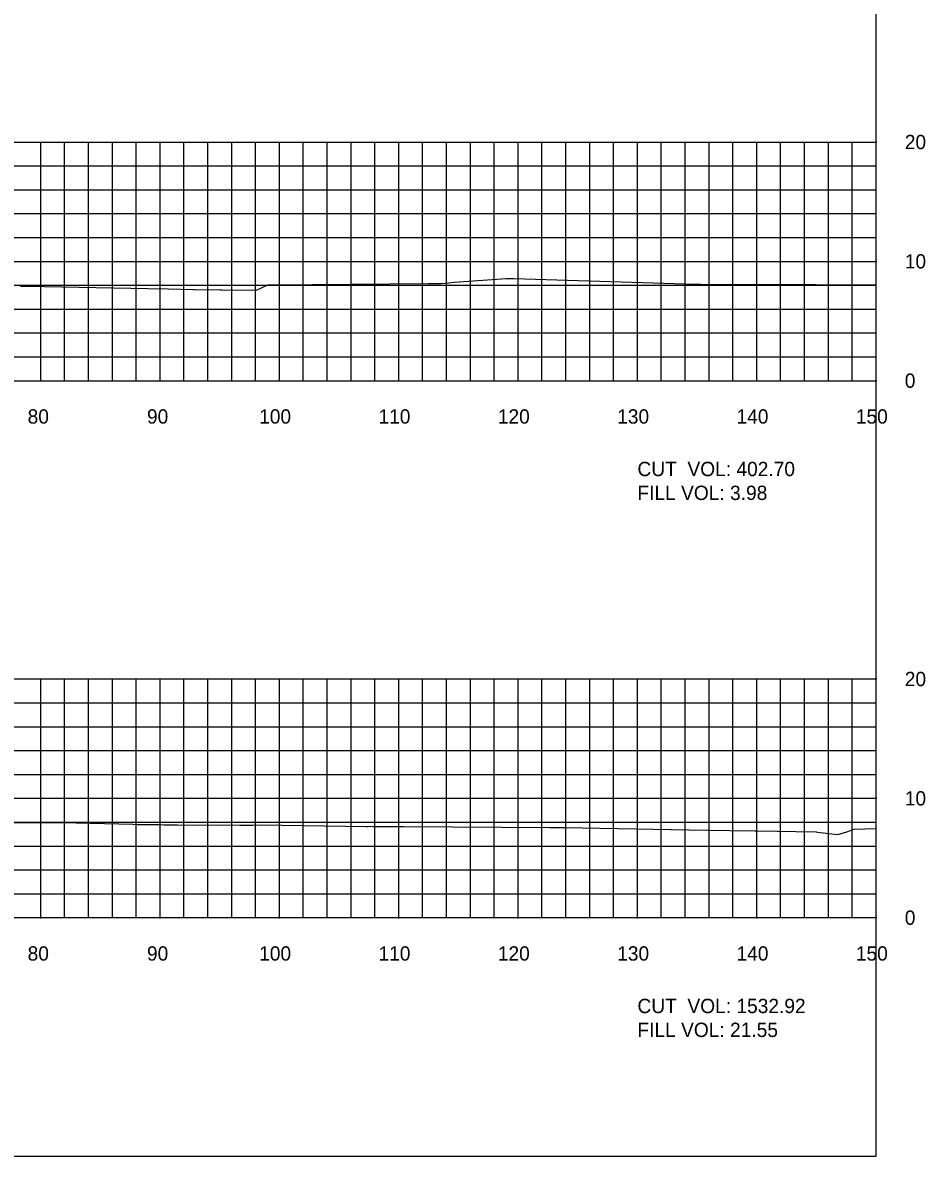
# Model space of a CAD drawing. Extents: x 1797419 to 1809236, y 248759 to 251512.
# Drawn here: x 1805429.5 to 1805505.1, y 250079.4 to 250174.4 of the extents above; entities that cross this region are included whole.
import ezdxf

# ---------------------------------------------------------------- set-up
doc = ezdxf.new("R2010")
doc.units = 0
for name, color, linetype in [('10', 7, 'Continuous'), ('31', 7, 'Continuous'), ('60', 7, 'Continuous'), ('ANNO-TXT', 7, 'Continuous'), ('Level 62', 7, 'Continuous'), ('M-ROADS', 7, 'Continuous')]:
    doc.layers.add(name, color=color, linetype=linetype)

msp = doc.modelspace()

# ---------------------------------------------------------------- linework, layer by layer
msp.add_lwpolyline([(1805201.002, 250079.432), (1805501.002, 250079.432), (1805501.002, 250269.432), (1805201.002, 250269.432)], close=True)
at = {"layer": '60'}
for p, q in [((1805501.002, 250144.432), (1805501.002, 250164.432)), ((1805501.062, 250164.432), (1805501.002, 250164.432)), ((1805501.062, 250154.432), (1805501.002, 250154.432)), ((1805201.002, 250144.432), (1805501.002, 250144.432)), ((1805431.002, 250144.372), (1805431.002, 250144.432)), ((1805441.002, 250144.372), (1805441.002, 250144.432)), ((1805451.002, 250144.372), (1805451.002, 250144.432)), ((1805461.002, 250144.372), (1805461.002, 250144.432)), ((1805471.002, 250144.372), (1805471.002, 250144.432)), ((1805481.002, 250144.372), (1805481.002, 250144.432)), ((1805491.002, 250144.372), (1805491.002, 250144.432)), ((1805501.002, 250144.372), (1805501.002, 250144.432)), ((1805501.062, 250144.432), (1805501.002, 250144.432)), ((1805501.002, 250099.432), (1805501.002, 250119.432)), ((1805501.062, 250119.432), (1805501.002, 250119.432)), ((1805501.062, 250109.432), (1805501.002, 250109.432)), ((1805201.002, 250099.432), (1805501.002, 250099.432)), ((1805431.002, 250099.372), (1805431.002, 250099.432)), ((1805441.002, 250099.372), (1805441.002, 250099.432)), ((1805451.002, 250099.372), (1805451.002, 250099.432)), ((1805461.002, 250099.372), (1805461.002, 250099.432)), ((1805471.002, 250099.372), (1805471.002, 250099.432)), ((1805481.002, 250099.372), (1805481.002, 250099.432)), ((1805491.002, 250099.372), (1805491.002, 250099.432)), ((1805501.002, 250099.372), (1805501.002, 250099.432)), ((1805501.062, 250099.432), (1805501.002, 250099.432))]:
    msp.add_line(p, q, dxfattribs=at)
at = {"layer": 'Level 62'}
for p, q in [((1805201.002, 250164.432), (1805501.002, 250164.432)), ((1805431.002, 250144.432), (1805431.002, 250164.432)), ((1805433.002, 250144.432), (1805433.002, 250164.432)), ((1805435.002, 250144.432), (1805435.002, 250164.432)), ((1805437.002, 250144.432), (1805437.002, 250164.432)), ((1805439.002, 250144.432), (1805439.002, 250164.432)), ((1805441.002, 250144.432), (1805441.002, 250164.432)), ((1805443.002, 250144.432), (1805443.002, 250164.432)), ((1805445.002, 250144.432), (1805445.002, 250164.432)), ((1805447.002, 250144.432), (1805447.002, 250164.432)), ((1805449.002, 250144.432), (1805449.002, 250164.432)), ((1805451.002, 250144.432), (1805451.002, 250164.432)), ((1805453.002, 250144.432), (1805453.002, 250164.432)), ((1805455.002, 250144.432), (1805455.002, 250164.432)), ((1805457.002, 250144.432), (1805457.002, 250164.432)), ((1805459.002, 250144.432), (1805459.002, 250164.432)), ((1805461.002, 250144.432), (1805461.002, 250164.432)), ((1805463.002, 250144.432), (1805463.002, 250164.432)), ((1805465.002, 250144.432), (1805465.002, 250164.432)), ((1805467.002, 250144.432), (1805467.002, 250164.432)), ((1805469.002, 250144.432), (1805469.002, 250164.432)), ((1805471.002, 250144.432), (1805471.002, 250164.432)), ((1805473.002, 250144.432), (1805473.002, 250164.432)), ((1805475.002, 250144.432), (1805475.002, 250164.432)), ((1805477.002, 250144.432), (1805477.002, 250164.432)), ((1805479.002, 250144.432), (1805479.002, 250164.432)), ((1805481.002, 250144.432), (1805481.002, 250164.432)), ((1805483.002, 250144.432), (1805483.002, 250164.432)), ((1805485.002, 250144.432), (1805485.002, 250164.432)), ((1805487.002, 250144.432), (1805487.002, 250164.432)), ((1805489.002, 250144.432), (1805489.002, 250164.432)), ((1805491.002, 250144.432), (1805491.002, 250164.432)), ((1805493.002, 250144.432), (1805493.002, 250164.432)), ((1805495.002, 250144.432), (1805495.002, 250164.432)), ((1805497.002, 250144.432), (1805497.002, 250164.432)), ((1805499.002, 250144.432), (1805499.002, 250164.432)), ((1805501.002, 250144.432), (1805501.002, 250164.432)), ((1805201.002, 250162.432), (1805501.002, 250162.432)), ((1805201.002, 250160.432), (1805501.002, 250160.432)), ((1805201.002, 250158.432), (1805501.002, 250158.432)), ((1805201.002, 250156.432), (1805501.002, 250156.432)), ((1805201.002, 250154.432), (1805501.002, 250154.432)), ((1805201.002, 250152.432), (1805501.002, 250152.432)), ((1805201.002, 250150.432), (1805501.002, 250150.432)), ((1805201.002, 250148.432), (1805501.002, 250148.432)), ((1805201.002, 250146.432), (1805501.002, 250146.432)), ((1805201.002, 250144.432), (1805501.002, 250144.432)), ((1805201.002, 250119.432), (1805501.002, 250119.432)), ((1805431.002, 250099.432), (1805431.002, 250119.432)), ((1805433.002, 250099.432), (1805433.002, 250119.432)), ((1805435.002, 250099.432), (1805435.002, 250119.432)), ((1805437.002, 250099.432), (1805437.002, 250119.432)), ((1805439.002, 250099.432), (1805439.002, 250119.432)), ((1805441.002, 250099.432), (1805441.002, 250119.432)), ((1805443.002, 250099.432), (1805443.002, 250119.432)), ((1805445.002, 250099.432), (1805445.002, 250119.432)), ((1805447.002, 250099.432), (1805447.002, 250119.432)), ((1805449.002, 250099.432), (1805449.002, 250119.432)), ((1805451.002, 250099.432), (1805451.002, 250119.432)), ((1805453.002, 250099.432), (1805453.002, 250119.432)), ((1805455.002, 250099.432), (1805455.002, 250119.432)), ((1805457.002, 250099.432), (1805457.002, 250119.432)), ((1805459.002, 250099.432), (1805459.002, 250119.432)), ((1805461.002, 250099.432), (1805461.002, 250119.432)), ((1805463.002, 250099.432), (1805463.002, 250119.432)), ((1805465.002, 250099.432), (1805465.002, 250119.432)), ((1805467.002, 250099.432), (1805467.002, 250119.432)), ((1805469.002, 250099.432), (1805469.002, 250119.432)), ((1805471.002, 250099.432), (1805471.002, 250119.432)), ((1805473.002, 250099.432), (1805473.002, 250119.432)), ((1805475.002, 250099.432), (1805475.002, 250119.432)), ((1805477.002, 250099.432), (1805477.002, 250119.432)), ((1805479.002, 250099.432), (1805479.002, 250119.432)), ((1805481.002, 250099.432), (1805481.002, 250119.432)), ((1805483.002, 250099.432), (1805483.002, 250119.432)), ((1805485.002, 250099.432), (1805485.002, 250119.432)), ((1805487.002, 250099.432), (1805487.002, 250119.432)), ((1805489.002, 250099.432), (1805489.002, 250119.432)), ((1805491.002, 250099.432), (1805491.002, 250119.432)), ((1805493.002, 250099.432), (1805493.002, 250119.432)), ((1805495.002, 250099.432), (1805495.002, 250119.432)), ((1805497.002, 250099.432), (1805497.002, 250119.432)), ((1805499.002, 250099.432), (1805499.002, 250119.432)), ((1805501.002, 250099.432), (1805501.002, 250119.432)), ((1805201.002, 250117.432), (1805501.002, 250117.432)), ((1805201.002, 250115.432), (1805501.002, 250115.432)), ((1805201.002, 250113.432), (1805501.002, 250113.432)), ((1805201.002, 250111.432), (1805501.002, 250111.432)), ((1805201.002, 250109.432), (1805501.002, 250109.432)), ((1805201.002, 250107.432), (1805501.002, 250107.432)), ((1805201.002, 250105.432), (1805501.002, 250105.432)), ((1805201.002, 250103.432), (1805501.002, 250103.432)), ((1805201.002, 250101.432), (1805501.002, 250101.432)), ((1805201.002, 250099.432), (1805501.002, 250099.432))]:
    msp.add_line(p, q, dxfattribs=at)
at = {"layer": 'M-ROADS'}
for points in [[(1805429.292, 250152.361), (1805429.907, 250152.354), (1805430.399, 250152.343), (1805430.502, 250152.341), (1805431.307, 250152.325), (1805438.547, 250152.196), (1805439.984, 250152.166), (1805441.706, 250152.128), (1805443.811, 250152.083), (1805443.871, 250152.082), (1805446.05, 250152.035), (1805446.21, 250152.033), (1805449.089, 250152.026), (1805450.043, 250152.468), (1805450.058, 250152.475), (1805450.126, 250152.475), (1805450.159, 250152.476), (1805453.785, 250152.501), (1805463.473, 250152.564), (1805464.148, 250152.568), (1805464.213, 250152.567), (1805464.228, 250152.567), (1805464.242, 250152.567), (1805464.451, 250152.571), (1805464.512, 250152.57), (1805464.537, 250152.574), (1805464.541, 250152.574), (1805465.205, 250152.639), (1805465.664, 250152.675), (1805469.995, 250152.99), (1805470.469, 250152.996), (1805470.578, 250152.998), (1805470.646, 250152.992), (1805471.566, 250152.972), (1805485.901, 250152.511), (1805486.278, 250152.516), (1805486.319, 250152.517), (1805494.925, 250152.486), (1805495.923, 250152.481), (1805497.504, 250152.472), (1805501.002, 250152.452)], [(1805424.428, 250107.402), (1805430.744, 250107.409), (1805431.33, 250107.41), (1805431.75, 250107.406), (1805431.801, 250107.405), (1805431.85, 250107.405), (1805431.927, 250107.405), (1805432.019, 250107.406), (1805432.055, 250107.405), (1805432.514, 250107.401), (1805432.568, 250107.399), (1805432.711, 250107.399), (1805432.808, 250107.399), (1805438.716, 250107.255), (1805439.105, 250107.249), (1805439.403, 250107.245), (1805439.699, 250107.24), (1805440.166, 250107.237), (1805440.681, 250107.234), (1805440.931, 250107.227), (1805441.355, 250107.215), (1805441.7, 250107.214), (1805442.049, 250107.213), (1805442.47, 250107.217), (1805447.679, 250107.188), (1805448.031, 250107.192), (1805448.752, 250107.196), (1805449.457, 250107.2), (1805458.302, 250107.084), (1805458.44, 250107.085), (1805458.538, 250107.086), (1805458.857, 250107.078), (1805458.948, 250107.076), (1805459.411, 250107.073), (1805459.674, 250107.074), (1805459.856, 250107.075), (1805459.943, 250107.085), (1805459.993, 250107.081), (1805460.19, 250107.069), (1805460.291, 250107.068), (1805460.568, 250107.068), (1805460.573, 250107.068), (1805460.838, 250107.067), (1805460.955, 250107.066), (1805461.356, 250107.069), (1805461.413, 250107.069), (1805473.69, 250106.988), (1805473.718, 250106.989), (1805473.755, 250106.99), (1805473.798, 250106.99), (1805474.35, 250106.983), (1805474.354, 250106.982), (1805474.355, 250106.982), (1805474.357, 250106.982), (1805474.36, 250106.982), (1805474.363, 250106.982), (1805474.364, 250106.982), (1805474.368, 250106.982), (1805474.381, 250106.982), (1805474.382, 250106.982), (1805474.925, 250106.983), (1805485.3, 250106.786), (1805486.914, 250106.762), (1805488.742, 250106.735), (1805490.83, 250106.704), (1805490.921, 250106.702), (1805492.717, 250106.675), (1805492.775, 250106.676), (1805494.27, 250106.653), (1805495.965, 250106.627), (1805496.058, 250106.609), (1805497.787, 250106.413), (1805498.543, 250106.615), (1805499.149, 250106.848), (1805501.002, 250106.913)]]:
    msp.add_lwpolyline(points, dxfattribs=at)

# ---------------------------------------------------------------- texts
at = {"layer": '10'}
for s, p in [('80', (1805429.901, 250140.832)), ('90', (1805439.901, 250140.832)), ('100', (1805449.301, 250140.832)), ('110', (1805459.301, 250140.832)), ('120', (1805469.301, 250140.832)), ('130', (1805479.301, 250140.832)), ('140', (1805489.301, 250140.832)), ('150', (1805499.301, 250140.832)), ('80', (1805429.901, 250095.832)), ('90', (1805439.901, 250095.832)), ('100', (1805449.301, 250095.832)), ('110', (1805459.301, 250095.832)), ('120', (1805469.301, 250095.832)), ('130', (1805479.301, 250095.832)), ('140', (1805489.301, 250095.832)), ('150', (1805499.301, 250095.832))]:
    msp.add_text(s, height=1.2, dxfattribs=at).set_placement(p)
at = {"layer": '31'}
for s, p in [('20', (1805503.402, 250163.832)), ('10', (1805503.402, 250153.832)), ('0', (1805503.402, 250143.832)), ('20', (1805503.402, 250118.832)), ('10', (1805503.402, 250108.832)), ('0', (1805503.402, 250098.832))]:
    msp.add_text(s, height=1.2, dxfattribs=at).set_placement(p)
at = {"layer": 'ANNO-TXT'}
for s, p in [('CUT  VOL: 402.70', (1805481.002, 250136.432)), ('FILL VOL: 3.98', (1805481.002, 250134.432)), ('CUT  VOL: 1532.92', (1805481.002, 250091.432)), ('FILL VOL: 21.55', (1805481.002, 250089.432))]:
    msp.add_text(s, height=1.2, dxfattribs=at).set_placement(p)

doc.saveas('drawing.dxf')
